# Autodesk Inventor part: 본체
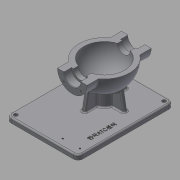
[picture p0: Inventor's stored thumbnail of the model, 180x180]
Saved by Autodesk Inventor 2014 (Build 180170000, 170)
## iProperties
Created: 2015-12
Part Number: 본체
Material: 일반
Document SubType Name: Modeling
Designer: mduedu
Density: 2.71 g/cm^3
Appearance: 기본값
Author: mduedu
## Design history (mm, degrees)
sketch "스케치1"
  geometry: L1 (-53, 0)-(53, 0); A1 r 53 centre (0, 0) between (53, 0) and (-53, 0); 2 further points
  constraints: 2 coincident, 2 end point, 2 point on circle, 1 centre point, 1 horizontal, 1 midpoint
  dimensions: "d0" = 53 radius of A1
revolve "회전1" sketch "스케치1" stored, may be unused: angle "d2" = 90 deg
feature "쉘1" dims "d11" = 10
node "작업 평면1"
sketch "스케치2"
  geometry: C1 r 31 at (0, 0); 1 further point
  constraints: 1 centre point, 1 coincident
  dimensions: "d4" = 62 diameter of C1
extrude "돌출1" join sketch "스케치2" stored distance "d5" = 10; taper "d6" = 0 deg
hole "구멍1" diameter "d14" = 35; stored, may be unused: countersink angle "d18" = 90 deg, drill point angle "d20" = 0 deg; dims "d12" = 10, "d13" = 10, "d15" = 6, "d16" = 4, "d17" = 2, "d19" = 16
hole "구멍2" diameter "d23" = 27; stored, may be unused: countersink angle "d27" = 90 deg, drill point angle "d29" = 0 deg; dims "d21" = 10, "d22" = 10, "d24" = 6, "d25" = 4, "d26" = 2, "d28" = 16
fillet "모깎기1" dims "d30" = 0.3
chamfer "모따기1" distance "d40" = 1; stored, may be unused: second distance "d41" = 2, angle "d42" = 45 deg
sketch "스케치4"
  geometry: L1 (0, 0)-(0, -25); L2 (0, 0)-(-17.678, -17.678); A1 r 25 centre (0, 0) between (-17.678, -17.678) and (0, -25); 1 further point
  constraints: 4 end point, 2 point on circle, 1 centre point, 1 coincident, 1 vertical
  dimensions: "d43" = 50 diameter of A1; "d47" = 45 deg angle of L1 L2
hole "구멍4" sketch "스케치4" at (-17.678, -17.678) diameter "d49" = 3.242; stored, may be unused: countersink angle "d53" = 90 deg, drill point angle "d55" = 118 deg; dims "d50" = 11, "d51" = 4, "d52" = 2, "d54" = 13
node "작업 평면3"
sketch "스케치6" dims "d22" = 10
  geometry: L1 (-70, -75)-(130, -75); L2 (130, -75)-(130, 75); L3 (130, 75)-(-70, 75); L4 (-70, 75)-(-70, -75); 2 further points
  constraints: 8 end point, 2 parallel, 1 coincident, 1 horizontal, 1 perpendicular
  dimensions: "d158" = 200 distance of L3.end L2.end; "d159" = 150 distance of L2.end L1.end; "d162" = 75 distance from line of L1 point (0, 0); "d163" = 70 distance from line of L4 point (0, 0)
extrude "돌출3" join sketch "스케치6" distance "d80" = 10; taper "d81" = 0 deg
sketch "스케치7"
  geometry: C1 r 20 at (0, 0); 2 further points
  constraints: 2 coincident, 1 centre point
  dimensions: "d82" = 40 diameter of C1
extrude "돌출4" join sketch "스케치7" stored distance "d84" = 10; taper "d85" = 0 deg
sketch "스케치8"
  geometry: 3 further points
  constraints: 2 coincident
hole "구멍6" sketch "스케치8" at (0, 0) diameter "d86" = 20; stored, may be unused: countersink angle "d90" = 90 deg, drill point angle "d92" = 118 deg; dims "d87" = 7, "d88" = 40, "d89" = 5, "d91" = 10
fillet "모깎기2" dims "d93" = 0.3
sketch "스케치9"
  geometry: L1 (-45, -75)-(-38.245, -36.692); L2 (70, -75)-(-130, -75) reference; A1 r 53 centre (0, 0) between (42.988, 31) and (42.988, -31) reference; 1 further point
  constraints: 2 end point, 1 coincident, 1 point on circle, 1 point on line
  dimensions: "d94" = 45 horizontal distance of L1.start point (0, 0); "d160" = 80 deg angle of L2 L1
feature "리브1" sketch "스케치9" dims "d96" = 1, "d97" = 8, "d98" = 0, "d99" = 0, "d100" = 1, "d101" = 1
fillet "모깎기3" dims "d120" = 3
fillet "모깎기4" dims "d121" = 3, "d122" = 3
fillet "모깎기5" dims "d123" = 3
sketch "스케치12"
  geometry: L1 (0, 100)-(0, -100); L2 (0, 100)-(100, 100); L3 (100, 100)-(100, -100); L4 (100, -100)-(0, -100); 2 further points
  constraints: 8 end point, 3 perpendicular, 1 coincident, 1 midpoint, 1 vertical
  dimensions: "d127" = 200 distance of L2.end L3.end; "d129" = 100 distance between parallel lines of L1 L3
extrude "돌출5" cut sketch "스케치12" stored distance "d130" = 10; taper "d131" = 0 deg
fillet "모깎기10" dims "d164" = 10
fillet "모깎기11" dims "d165" = 3
sketch "스케치15"
  geometry: C1 r 4 at (-120, 65); C2 r 4 at (60, 65); C3 r 4 at (60, -65); A1 r 10 centre (-120, 65) between (-120, 75) and (-130, 65) reference; A2 r 10 centre (60, 65) between (70, 65) and (60, 75) reference; A3 r 10 centre (60, -65) between (60, -75) and (70, -65) reference; 1 further point
  constraints: 3 centre point, 3 coincident, 2 equal radius
  dimensions: "d166" = 8 diameter of C1
extrude "돌출8" cut sketch "스케치15" stored distance "d167" = 10; taper "d168" = 0 deg
sketch "스케치16"
  geometry: L1 (-130, 65)-(-130, -65) reference; L2 (-120, -75)-(60, -75) reference; 2 further points
  constraints: 1 other
  dimensions: "d169" = 70 distance from line of point (-60, -55) L1; "d170" = 20 distance from line of point (-60, -55) L2
feature "엠보싱2" sketch "스케치16" dims "d171" = 0.5, "d172" = 0
sketch "스케치17"
  geometry: L1 (-120, 75)-(60, 75) reference; L2 (-130, -65)-(-130, 65) reference; 2 further points
  constraints: 1 vertical alignment
  dimensions: "d180" = 12 distance from line of L1 point (-114, 63); "d181" = 16 distance from line of point (-114, 63) L2; "d182" = 36 distance of point (-114, 27) point (-114, 63)
hole "구멍9" sketch "스케치17" at (-114, 63), (-114, 27) diameter "d173" = 3.242; stored, may be unused: countersink angle "d177" = 90 deg, drill point angle "d179" = 0 deg; dims "d174" = 6, "d175" = 4, "d176" = 2, "d178" = 8
node "솔리드1"
mirror "대칭1"
mirror "대칭2"
pattern_circular "원형 패턴1" dims angle "d57" = 360 deg
mirror "대칭3"
pattern_circular "원형 패턴3" dims angle "d103" = 360 deg
other parameters: "d3" = 67, "d77" = -85
